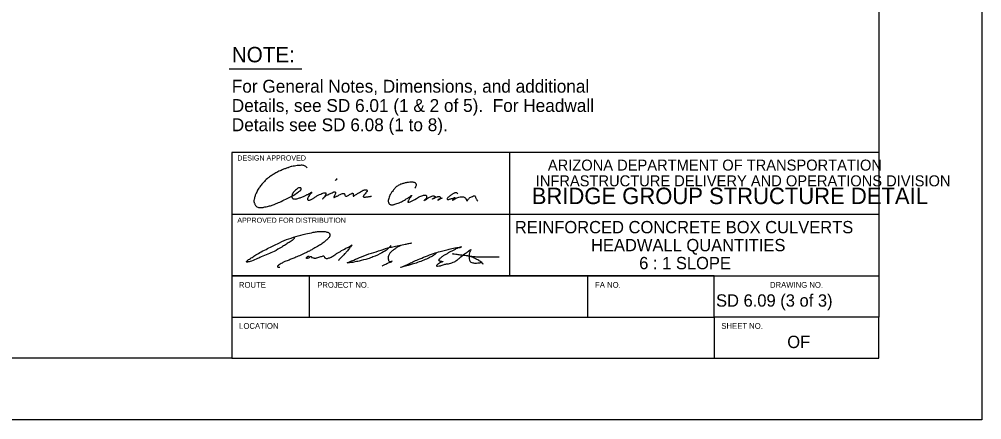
# Model space of a CAD drawing. Extents: x -0.08 to 2.83, y -0.03 to 1.92.
# Drawn here: x 1.859 to 2.833, y 0 to 0.406 of the extents above; entities that cross this region are included whole.
import ezdxf

# ---------------------------------------------------------------- set-up
doc = ezdxf.new("R2010")
doc.units = 0
for name, color, linetype in [('55', 7, 'Continuous'), ('57', 7, 'Continuous'), ('62', 7, 'Continuous'), ('63', 7, 'Continuous')]:
    doc.layers.add(name, color=color, linetype=linetype)

msp = doc.modelspace()

# ---------------------------------------------------------------- linework, layer by layer
at = {"layer": '55'}
for points in [[(2.15001, 0.25543), (2.14758, 0.25741), (2.14617, 0.25785), (2.14423, 0.25794), (2.14225, 0.25776), (2.1402, 0.25761), (2.13722, 0.2572), (2.13461, 0.25674), (2.13312, 0.25633), (2.13139, 0.2557), (2.1309, 0.25548), (2.1279, 0.25446), (2.12484, 0.2532), (2.1206, 0.25132), (2.11648, 0.24906), (2.11297, 0.24683), (2.10987, 0.24445), (2.10588, 0.24062), (2.10299, 0.237), (2.10059, 0.23378), (2.09857, 0.22978), (2.09735, 0.22698), (2.09658, 0.22347), (2.09632, 0.22083), (2.0965, 0.22021), (2.09681, 0.21951), (2.09723, 0.21833), (2.098, 0.21721), (2.09936, 0.21582), (2.101, 0.2152), (2.10355, 0.21505), (2.10736, 0.21566), (2.10994, 0.21625), (2.11399, 0.21726), (2.11746, 0.21865), (2.1224, 0.22067), (2.12858, 0.22356), (2.13414, 0.22632), (2.14122, 0.23075), (2.14355, 0.23265), (2.1438, 0.23291), (2.14403, 0.23351), (2.14403, 0.23426), (2.14395, 0.23467), (2.14366, 0.23506), (2.14306, 0.23523), (2.14231, 0.23519), (2.14138, 0.23496), (2.14015, 0.23417), (2.13831, 0.23262), (2.1366, 0.23096), (2.1355, 0.22937), (2.13485, 0.2278), (2.13469, 0.22641), (2.13471, 0.22546), (2.13499, 0.22483), (2.13551, 0.2243), (2.13614, 0.22393), (2.13712, 0.22378), (2.13865, 0.22378), (2.14061, 0.22424), (2.1439, 0.22538), (2.14709, 0.22656), (2.14964, 0.22791), (2.15235, 0.22918), (2.1548, 0.23064), (2.15321, 0.22863), (2.15278, 0.22814), (2.15212, 0.22718), (2.15124, 0.22569), (2.15055, 0.22402), (2.15062, 0.22327), (2.15113, 0.2227), (2.15171, 0.22264), (2.15353, 0.2229), (2.15492, 0.22351), (2.15731, 0.22511), (2.15997, 0.22683), (2.16276, 0.22826), (2.16513, 0.22931), (2.1672, 0.22997), (2.16877, 0.23003), (2.16885, 0.23001), (2.16905, 0.22994), (2.16916, 0.22971), (2.16921, 0.22923), (2.16902, 0.22873), (2.16846, 0.22743), (2.1677, 0.22608), (2.16569, 0.22382), (2.16628, 0.22431), (2.16828, 0.22641), (2.16883, 0.2268), (2.16988, 0.2275), (2.1711, 0.22812), (2.17281, 0.229), (2.17455, 0.2298), (2.17652, 0.23053), (2.17805, 0.23107), (2.17845, 0.23099), (2.17884, 0.23056), (2.17886, 0.22947), (2.17831, 0.22798), (2.17796, 0.22723), (2.17731, 0.22578), (2.17716, 0.22546), (2.17716, 0.22538), (2.17753, 0.22539), (2.17821, 0.22565), (2.17895, 0.22596), (2.18003, 0.22647), (2.18113, 0.22707), (2.18425, 0.22854), (2.18595, 0.22925), (2.18701, 0.22947), (2.18751, 0.22945), (2.18764, 0.22938), (2.18777, 0.22927), (2.18805, 0.22878), (2.18849, 0.22777), (2.18919, 0.22648), (2.1903, 0.2268), (2.19162, 0.22742), (2.19305, 0.22818), (2.19472, 0.22898), (2.1958, 0.22955), (2.19618, 0.2297), (2.19652, 0.22948), (2.19677, 0.22899), (2.19681, 0.22851), (2.19688, 0.22708), (2.19689, 0.22654), (2.19699, 0.2265), (2.19794, 0.22713), (2.20054, 0.22882), (2.20306, 0.23041), (2.20516, 0.23164), (2.20697, 0.23255), (2.20839, 0.23299), (2.21006, 0.23312), (2.2106, 0.23289), (2.21082, 0.23247), (2.2109, 0.23199), (2.21081, 0.23152), (2.2104, 0.23086), (2.20965, 0.2299), (2.20831, 0.22816), (2.20712, 0.22678), (2.20699, 0.22618), (2.20715, 0.22586), (2.2085, 0.22567), (2.20942, 0.22576), (2.21055, 0.22588), (2.21161, 0.22603), (2.21247, 0.22616), (2.21418, 0.22636), (2.21539, 0.22668)], [(2.17986, 0.24471), (2.17999, 0.24419), (2.17945, 0.24328), (2.17891, 0.24254), (2.18016, 0.24389), (2.18061, 0.24401)], [(2.25913, 0.23472), (2.26029, 0.23637), (2.26076, 0.23774), (2.26076, 0.23856), (2.26062, 0.23911), (2.26004, 0.23992), (2.25945, 0.24026), (2.2583, 0.24058), (2.25644, 0.2408), (2.25422, 0.2407), (2.25114, 0.2404), (2.24777, 0.23963), (2.2448, 0.23864), (2.24155, 0.23685), (2.23882, 0.23456), (2.2377, 0.23304), (2.2365, 0.23153), (2.23482, 0.22905), (2.23317, 0.22562), (2.23251, 0.22313), (2.2323, 0.22157), (2.2325, 0.22061), (2.23275, 0.2199), (2.23334, 0.21882), (2.23414, 0.21819), (2.23498, 0.21801), (2.2361, 0.21789), (2.23696, 0.21795), (2.23781, 0.21809), (2.23899, 0.21844), (2.24106, 0.21913), (2.24338, 0.21998), (2.24568, 0.22106), (2.24791, 0.22222), (2.25148, 0.22431), (2.25408, 0.22593), (2.25528, 0.22699), (2.25596, 0.22758), (2.2558, 0.22724), (2.25569, 0.22701), (2.25442, 0.2253), (2.25333, 0.22375), (2.25269, 0.22234), (2.25245, 0.22167), (2.25221, 0.22097), (2.25221, 0.22077), (2.25227, 0.22059), (2.25263, 0.22047), (2.25298, 0.22053), (2.2536, 0.22067), (2.25502, 0.22125), (2.26074, 0.22419), (2.26545, 0.22673), (2.26732, 0.22736), (2.26877, 0.22774), (2.26999, 0.22768), (2.27076, 0.22738), (2.27111, 0.22675), (2.27112, 0.22556), (2.27102, 0.22481), (2.27061, 0.22411), (2.26819, 0.22181), (2.27093, 0.22373), (2.27398, 0.22556), (2.27644, 0.22654), (2.27843, 0.22689), (2.27927, 0.22661), (2.27985, 0.2258), (2.27977, 0.22554), (2.27976, 0.22537), (2.27941, 0.22518), (2.2786, 0.22453), (2.27706, 0.22375), (2.27972, 0.22513), (2.28179, 0.22589), (2.28256, 0.22619), (2.28403, 0.22629), (2.28469, 0.22599), (2.28517, 0.22525), (2.28515, 0.22471), (2.28492, 0.22428), (2.28393, 0.22344), (2.28235, 0.22249), (2.28532, 0.22412), (2.28733, 0.22492)], [(2.30267, 0.22892), (2.30234, 0.22949), (2.3018, 0.22993), (2.30131, 0.23009), (2.3008, 0.23009), (2.30032, 0.23003), (2.29957, 0.22989), (2.29894, 0.22961), (2.29775, 0.22894), (2.29677, 0.22833), (2.29582, 0.22761), (2.29429, 0.22651), (2.29321, 0.22567), (2.29216, 0.2246), (2.29189, 0.22405), (2.2918, 0.22362), (2.29182, 0.22366), (2.29199, 0.22348), (2.29251, 0.22335), (2.2936, 0.22339), (2.29501, 0.22377), (2.29629, 0.22413), (2.29798, 0.2247), (2.29932, 0.22536), (2.29957, 0.22541), (2.29976, 0.2253), (2.29981, 0.2252), (2.29975, 0.225), (2.29959, 0.2248), (2.29831, 0.22373), (2.29744, 0.22287), (2.29735, 0.22276), (2.29743, 0.2227), (2.29781, 0.22277), (2.2988, 0.22329), (2.30057, 0.22435), (2.30188, 0.225), (2.30392, 0.22573), (2.3061, 0.22604), (2.30849, 0.22581), (2.30949, 0.22544), (2.31036, 0.22475), (2.31091, 0.22411), (2.3116, 0.22265), (2.31196, 0.22161), (2.3126, 0.22233), (2.31334, 0.22346), (2.31434, 0.22457), (2.31582, 0.22566), (2.31756, 0.2264), (2.31949, 0.22699), (2.31976, 0.22691), (2.32023, 0.22668), (2.3207, 0.22516), (2.32126, 0.22398), (2.32189, 0.22286), (2.32233, 0.22209), (2.32292, 0.22145)], [(2.13692, 0.18516), (2.13711, 0.18449), (2.13708, 0.18402), (2.13681, 0.18349), (2.13589, 0.18255), (2.13195, 0.17982), (2.12821, 0.17738), (2.12437, 0.17504), (2.11671, 0.17069), (2.10374, 0.16502), (2.10229, 0.16443), (2.09999, 0.1634), (2.09376, 0.16092), (2.09139, 0.16014), (2.09018, 0.15994), (2.08919, 0.15985), (2.08904, 0.15989), (2.08875, 0.16017), (2.08886, 0.16035), (2.08914, 0.16074), (2.09001, 0.16165), (2.09361, 0.16401), (2.0971, 0.16634), (2.1021, 0.16941), (2.10864, 0.17274), (2.11998, 0.17836), (2.1292, 0.18259), (2.13862, 0.18561), (2.14876, 0.18833), (2.15642, 0.19001), (2.16054, 0.19071), (2.1641, 0.1909), (2.16637, 0.19094), (2.1683, 0.19075), (2.17023, 0.19028), (2.1718, 0.18974), (2.17245, 0.18918), (2.17281, 0.18877), (2.17307, 0.18808), (2.17324, 0.18741), (2.17323, 0.18698), (2.17317, 0.1864), (2.17305, 0.18598), (2.17272, 0.18537), (2.17195, 0.18431), (2.17071, 0.18308), (2.16807, 0.18073), (2.16459, 0.17812), (2.16054, 0.17558), (2.15565, 0.17281), (2.15245, 0.171), (2.14775, 0.16877), (2.14512, 0.16756), (2.13957, 0.16509), (2.1355, 0.16347), (2.13193, 0.16192), (2.12769, 0.16032), (2.12482, 0.15889), (2.12278, 0.15776), (2.12183, 0.1571), (2.12131, 0.15676), (2.12086, 0.15632), (2.12046, 0.15586), (2.12012, 0.15542), (2.12011, 0.15537), (2.12011, 0.15526), (2.1202, 0.15509), (2.12036, 0.15488), (2.12062, 0.15472), (2.12115, 0.15459), (2.12156, 0.15459), (2.12236, 0.15462), (2.12266, 0.15463)], [(2.15215, 0.16533), (2.15165, 0.16558), (2.15087, 0.16542), (2.1497, 0.16466), (2.14918, 0.16411), (2.14918, 0.16383), (2.1495, 0.16362), (2.15043, 0.16388), (2.15113, 0.16407), (2.15248, 0.16463), (2.15357, 0.16535), (2.15403, 0.16543), (2.15418, 0.16544), (2.15443, 0.16515), (2.1544, 0.16455), (2.15476, 0.16431), (2.15544, 0.16432), (2.15619, 0.16415), (2.15697, 0.16398), (2.15772, 0.16378), (2.15893, 0.16383), (2.1601, 0.16421), (2.16212, 0.16481), (2.16403, 0.16537), (2.16566, 0.16582), (2.16712, 0.16606), (2.16767, 0.16496), (2.16804, 0.16429), (2.1689, 0.16384), (2.17004, 0.16347), (2.17128, 0.16384), (2.17298, 0.16426), (2.1762, 0.16591), (2.18, 0.16838), (2.18508, 0.17145), (2.19087, 0.17445), (2.1937, 0.17599), (2.19558, 0.1773), (2.19408, 0.17539), (2.19361, 0.17483), (2.193, 0.17404), (2.19158, 0.17212), (2.19036, 0.17057), (2.18805, 0.16806), (2.18628, 0.16609), (2.18362, 0.16346), (2.18164, 0.16142)], [(2.23491, 0.17651), (2.23186, 0.17315), (2.22584, 0.16918), (2.21679, 0.16499), (2.21159, 0.16321), (2.20276, 0.1609), (2.19747, 0.15972), (2.19293, 0.15912), (2.19072, 0.15909), (2.19235, 0.15989), (2.19737, 0.16193), (2.20515, 0.16517), (2.21517, 0.16888), (2.22498, 0.17188), (2.23419, 0.17479), (2.23965, 0.17583), (2.24639, 0.17729), (2.25314, 0.1786), (2.25576, 0.17906), (2.25005, 0.17775), (2.24376, 0.17607), (2.24298, 0.17572), (2.24203, 0.1753), (2.24067, 0.17435), (2.23819, 0.17259), (2.23585, 0.17076), (2.2335, 0.16821), (2.23281, 0.1669), (2.23236, 0.16519), (2.23225, 0.16307), (2.23247, 0.16233), (2.2327, 0.16154), (2.23327, 0.16046), (2.23374, 0.16008), (2.23426, 0.15985), (2.23515, 0.16001), (2.23578, 0.16029), (2.2364, 0.16088), (2.23548, 0.16053), (2.23352, 0.15952), (2.23198, 0.15863), (2.23092, 0.15801), (2.22859, 0.15697), (2.227, 0.15624), (2.22607, 0.15571)], [(2.28075, 0.16875), (2.27797, 0.16654), (2.27366, 0.16413), (2.26825, 0.16177), (2.26206, 0.15933), (2.25657, 0.15761), (2.25242, 0.15648), (2.24459, 0.1543), (2.24926, 0.15636), (2.25262, 0.1578), (2.25725, 0.16014), (2.26258, 0.16247), (2.26991, 0.16539), (2.27822, 0.16854), (2.28481, 0.17056), (2.29031, 0.17203), (2.29538, 0.17324), (2.30109, 0.17436), (2.30588, 0.17543), (2.30606, 0.17546), (2.30606, 0.17525), (2.30316, 0.17414), (2.3009, 0.17315), (2.29924, 0.17223), (2.29807, 0.17157), (2.29507, 0.17014), (2.29189, 0.16831), (2.28907, 0.16674), (2.28671, 0.16521), (2.28453, 0.16333), (2.28365, 0.16246), (2.28334, 0.16199), (2.28345, 0.1616), (2.28392, 0.16118), (2.28531, 0.16081), (2.28728, 0.16045), (2.28749, 0.16038), (2.28753, 0.16024), (2.28657, 0.15987), (2.2841, 0.15862), (2.28248, 0.15764), (2.2816, 0.15684), (2.28122, 0.15623), (2.28119, 0.15602), (2.28133, 0.15581), (2.28226, 0.15582), (2.28517, 0.15615), (2.28673, 0.1566), (2.28889, 0.15734), (2.29045, 0.15779), (2.29226, 0.15803), (2.29432, 0.15824), (2.29669, 0.15913), (2.29931, 0.16013), (2.30238, 0.16221), (2.30477, 0.16406), (2.30941, 0.16804), (2.31103, 0.1692), (2.31434, 0.17146), (2.31581, 0.17269), (2.31451, 0.16933), (2.31413, 0.1664), (2.31439, 0.16328), (2.31521, 0.16058), (2.31694, 0.1594), (2.32065, 0.15881), (2.32285, 0.15892), (2.32308, 0.15901), (2.32329, 0.15919), (2.32353, 0.15911), (2.32364, 0.159), (2.32467, 0.15907), (2.32563, 0.1593), (2.32699, 0.15903), (2.32804, 0.15819), (2.32817, 0.1581), (2.32825, 0.15812), (2.32825, 0.1582), (2.32813, 0.15837), (2.32721, 0.15911), (2.32701, 0.15927), (2.32506, 0.16076), (2.32392, 0.16151), (2.32032, 0.16332), (2.31627, 0.16522), (2.315, 0.16561), (2.31286, 0.166), (2.30979, 0.16645), (2.30602, 0.16682), (2.30209, 0.16741), (2.29903, 0.16786), (2.29731, 0.16826), (2.30287, 0.16758), (2.31104, 0.16647), (2.31894, 0.16545), (2.32442, 0.16523), (2.33099, 0.16521), (2.3432, 0.1651), (2.34473, 0.16507)]]:
    msp.add_spline(points, degree=3, dxfattribs=at)
at = {"layer": '57'}
msp.add_line((2.07131, 0.3556), (2.14477, 0.3556), dxfattribs=at)
at = {"layer": '63'}
for p, q in [((2.83333, 1.83333), (2.83333, 0)), ((2.72918, 0.27077), (2.07387, 0.27077)), ((2.07387, 0.27077), (2.07387, 0.06244)), ((2.35493, 0.27077), (2.35493, 0.14578)), ((2.57284, 0.27077), (2.57284, 0.27077)), ((2.07387, 0.20828), (2.72918, 0.20828)), ((2.07387, 0.20647), (2.07387, 0.20647)), ((2.07387, 0.20647), (2.07387, 0.20647)), ((2.07387, 0.14578), (2.72918, 0.14578)), ((2.07387, 0.14397), (2.07387, 0.14397)), ((2.08908, 0.14583), (2.08931, 0.14583)), ((2.15266, 0.10411), (2.15266, 0.14578)), ((2.23742, 0.14583), (2.23742, 0.14583)), ((2.23742, 0.14583), (2.23742, 0.14583)), ((2.23742, 0.14583), (2.23742, 0.14583)), ((2.23742, 0.14583), (2.23742, 0.14583)), ((2.43435, 0.10411), (2.43435, 0.14578)), ((2.07387, 0.10411), (2.56251, 0.10411)), ((2.56251, 0.10411), (2.56251, 0.06244)), ((2.72918, 0.06244), (2.72918, 0.10411)), ((2.07387, 0.06244), (2.72918, 0.06244)), ((2.83333, 0), (0, 0)), ((2.83, 0.00033), (2.83, 0.00033))]:
    msp.add_line(p, q, dxfattribs=at)
msp.add_lwpolyline([(0.16668, 0.06244), (0.16668, 1.77077), (2.72918, 1.77077), (2.72918, 0.10411), (2.56251, 0.10411), (2.56251, 0.14578), (2.07387, 0.14578), (2.07387, 0.06244)], close=True, dxfattribs=at)

# ---------------------------------------------------------------- texts
at = {"layer": '55'}
for s, p in [('DESIGN APPROVED', (2.07944, 0.26274)), ('APPROVED FOR DISTRIBUTION', (2.07944, 0.19966))]:
    msp.add_text(s, height=0.0052084, dxfattribs=at).set_placement(p)
at = {"layer": '57'}
for s, height, p in [('NOTE:', 0.015625, (2.07387, 0.36231)), ('For General Notes, Dimensions, and additional', 0.0130208, (2.07387, 0.33154)), ('Details, see SD 6.01 (1 & 2 of 5).  For Headwall', 0.0130208, (2.07387, 0.31201)), ('Details see SD 6.08 (1 to 8).', 0.0130208, (2.07387, 0.29248))]:
    msp.add_text(s, height=height, dxfattribs=at).set_placement(p)
at = {"layer": '62'}
for s, p in [('REINFORCED CONCRETE BOX CULVERTS', (2.3605, 0.189)), ('HEADWALL QUANTITIES', (2.43762, 0.17078)), ('6 : 1 SLOPE', (2.48643, 0.15255)), ('SD 6.09 (3 of 3)', (2.56425, 0.11464))]:
    msp.add_text(s, height=0.0125, dxfattribs=at).set_placement(p)
at = {"layer": '63'}
for s, height, p in [('ARIZONA DEPARTMENT OF TRANSPORTATION', 0.0111083, (2.39394, 0.25258)), ('INFRASTRUCTURE DELIVERY AND OPERATIONS DIVISION', 0.0111083, (2.38162, 0.23663)), ('BRIDGE GROUP STRUCTURE DETAIL', 0.0166667, (2.37762, 0.2186)), ('ROUTE', 0.005833, (2.08105, 0.13383)), ('PROJECT NO.', 0.0058333, (2.16034, 0.13383)), ('FA NO.', 0.005833, (2.44175, 0.13383)), ('DRAWING NO.', 0.0058334, (2.61888, 0.13383)), ('LOCATION', 0.005833, (2.08128, 0.09217)), ('SHEET NO.', 0.005833, (2.56964, 0.09217)), ('OF', 0.0125, (2.63638, 0.0727))]:
    msp.add_text(s, height=height, dxfattribs=at).set_placement(p)

doc.saveas('drawing.dxf')
